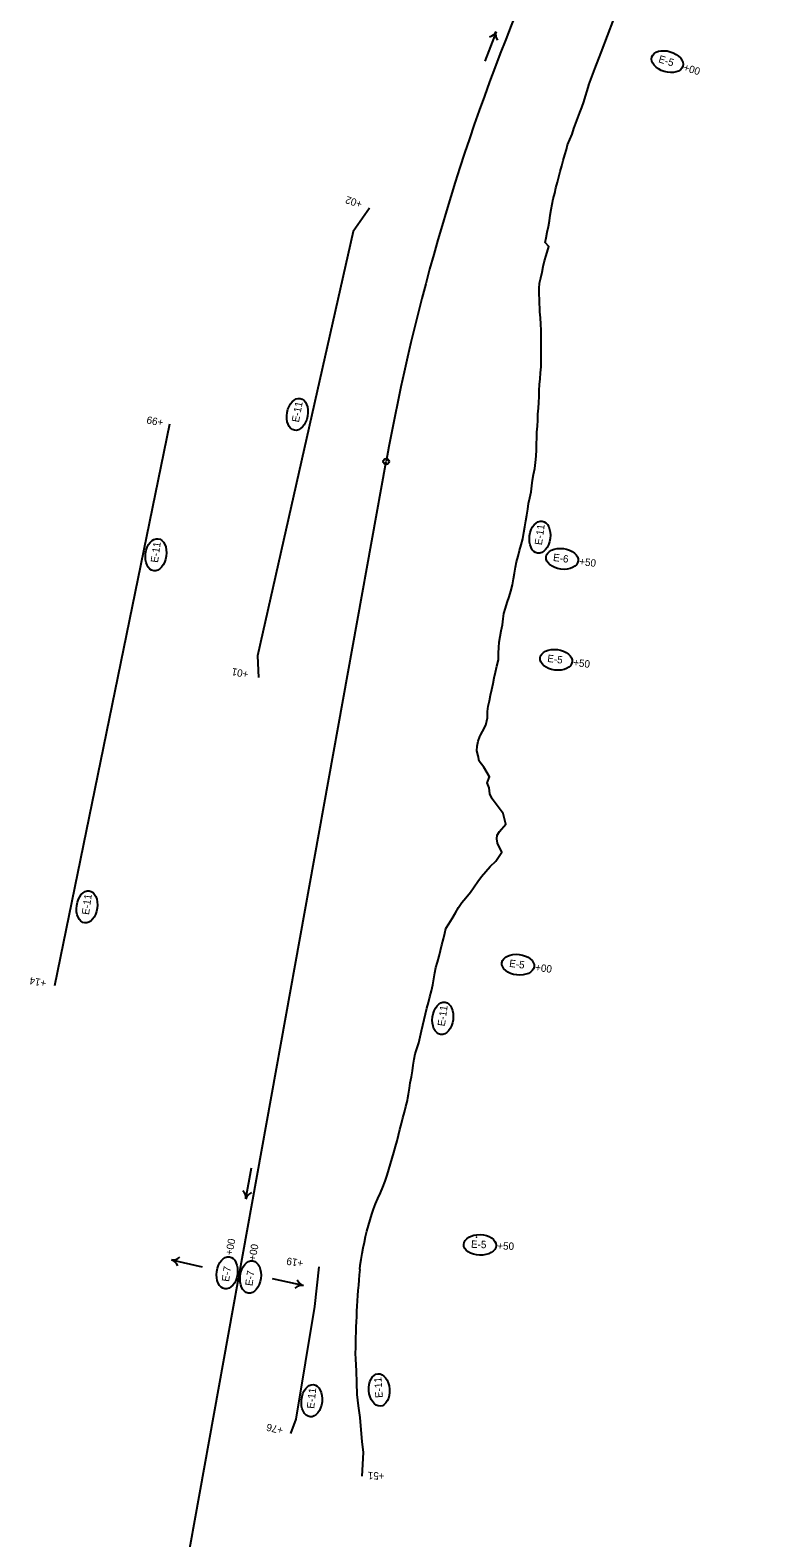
# Model space of a CAD drawing. Extents: x 669236 to 673912, y 735758 to 754788.
# Drawn here: x 670959 to 671572, y 744229 to 745505 of the extents above; entities that cross this region are included whole.
import ezdxf

# ---------------------------------------------------------------- set-up
doc = ezdxf.new("R2010")
doc.units = 0
for name, color, linetype in [('Default', 7, 'Continuous'), ('Prop_Horiz Alignment', 7, 'Continuous'), ('R_Erosion', 7, 'Continuous'), ('R_Erosion_1a', 7, 'Continuous'), ('R_Erosion_2', 7, 'Continuous'), ('R_Erosion_3', 7, 'Continuous'), ('R_Flow Arrows', 7, 'Continuous'), ('S_MSC_PT_SYM', 7, 'Continuous')]:
    doc.layers.add(name, color=color, linetype=linetype)

msp = doc.modelspace()

# ---------------------------------------------------------------- linework, layer by layer
at = {"layer": 'Default'}
msp.add_line((670962.6, 743492), (671260.2, 745139.8), dxfattribs=at)
msp.add_arc((673139.7, 744800.4), 1909.9, 145.1701, 169.7611, dxfattribs=at)
at = {"layer": 'Prop_Horiz Alignment'}
msp.add_circle((671260.2, 745139.8), 2.5, dxfattribs=at)
at = {"layer": 'R_Erosion'}
msp.add_line((671412.6, 745403.8), (671413.6, 745407.8), dxfattribs=at)
for points in [[(671431.6, 745458.5), (671436.7, 745471.9), (671442, 745485.9), (671447.3, 745500), (671452.6, 745513.9), (671457.5, 745526.2), (671463.1, 745540.1), (671469, 745553.8), (671475, 745567.6), (671480.8, 745581.5), (671486.6, 745595.3), (671492.4, 745609.1), (671498.5, 745622.7), (671504, 745634.7), (671510.1, 745648.3), (671517, 745661.5), (671517.6, 745662.6)], [(671413.6, 745407.8), (671415.5, 745412.2), (671417.4, 745416.8), (671419, 745421.4), (671420.6, 745426), (671422.2, 745430.5), (671423.9, 745435), (671425.6, 745439.4), (671427.3, 745444.1), (671428.7, 745448.9), (671430.1, 745453.5), (671431.6, 745458.3), (671431.6, 745458.5)], [(671394.8, 745325.2), (671395.5, 745329), (671396.4, 745333.7), (671397.4, 745338.5), (671398.3, 745343.3), (671399, 745348.2), (671399.8, 745353), (671400.5, 745357.6), (671401.5, 745362.1), (671402.7, 745366.7), (671403.8, 745371.4), (671405, 745376), (671406.1, 745380.6), (671407.4, 745385.2), (671408.7, 745389.9), (671409.9, 745394.5), (671411.2, 745399.2), (671412.6, 745403.8)], [(671248.6, 744504.8), (671249.4, 744507.2), (671251.3, 744511.8), (671253.2, 744516.4), (671255.3, 744521), (671257.5, 744525.8), (671259.5, 744530.9), (671261, 744536), (671262.4, 744540.7), (671263.9, 744545.5), (671265.3, 744550.4), (671266.8, 744555.3), (671268.1, 744560.2), (671269.4, 744565.1), (671270.6, 744570), (671271.9, 744574.8), (671273.2, 744579.7), (671274.4, 744584.6), (671275.6, 744589.4), (671276.9, 744594.2), (671278.2, 744599.3), (671278.6, 744601.5), (671279.1, 744604.6), (671279.8, 744609.5), (671280.6, 744614.2), (671281.6, 744619.2), (671282.4, 744624.3), (671283.1, 744629.2), (671283.9, 744634.1), (671284.6, 744638.6), (671286.1, 744643), (671287.8, 744648), (671289, 744653.1), (671290.2, 744658.1), (671291.1, 744663), (671292.3, 744667.6), (671293.6, 744672.6), (671294.7, 744677.4), (671296, 744682.2), (671297.2, 744687), (671298.6, 744691.9), (671299.8, 744697.1), (671300.6, 744702.2), (671301.5, 744707.1), (671302.3, 744711.8), (671303.5, 744716.3), (671304.9, 744721.2), (671306.1, 744726.1), (671307.4, 744730.9), (671308.7, 744735.9), (671309.7, 744740.8), (671310.8, 744744.6), (671313.3, 744748.6), (671316.1, 744753.3), (671318.8, 744757.9), (671321.4, 744762.4), (671324.1, 744766.6), (671327.6, 744770.7), (671331.5, 744775.4), (671334.5, 744780.1), (671337.7, 744784.4), (671340.9, 744788.8), (671344.4, 744793), (671348.1, 744797.1), (671353, 744801.6), (671358, 744809.3), (671354.3, 744816.9), (671353.8, 744820.5), (671354.2, 744823.6), (671356.1, 744826.9), (671361.5, 744833), (671359.1, 744842.1), (671354.2, 744848.7), (671349.9, 744854.3), (671348, 744858.6), (671347.4, 744863.7), (671345.6, 744867.9), (671347.5, 744873), (671342.8, 744881.1), (671338.9, 744886.4), (671338, 744890.7), (671336.9, 744895.1), (671337.3, 744899), (671338, 744903.3), (671339.3, 744907.2), (671340, 744908.4), (671341.6, 744911.4), (671344.5, 744916.7), (671345.9, 744922.9), (671346, 744928.3), (671346.5, 744932.7), (671347.5, 744937.4), (671348.4, 744942.1), (671349.7, 744947), (671350.7, 744952.1), (671351.6, 744956.9), (671352.8, 744961.7), (671353.8, 744966.6), (671355.1, 744972), (671355.2, 744977.6), (671355.4, 744982.5), (671355.8, 744987.1), (671356.6, 744991.8), (671357.5, 744996.6), (671358.5, 745001.7), (671359.2, 745006.8), (671359.8, 745011.3), (671361.2, 745015.6), (671362.6, 745020.5), (671364.1, 745025.3), (671365.6, 745030.2), (671366.9, 745035.4), (671367.9, 745040.5), (671368.8, 745045.4), (671369.7, 745050.3), (671370.5, 745055), (671371.8, 745059.7), (671373.1, 745064.5), (671374.4, 745069.4), (671375.7, 745074.5), (671376.6, 745079.6), (671377.4, 745084.6), (671378.2, 745089.5), (671379.1, 745094.5), (671379.9, 745099.4), (671380.7, 745104.2), (671381.7, 745109), (671382.7, 745114.2), (671383.3, 745119.3), (671383.9, 745124.1), (671384.9, 745128.8), (671385.8, 745134), (671386.4, 745139.1), (671387, 745144.3), (671387.2, 745149.6), (671387.4, 745154.7), (671387.5, 745159.7), (671387.7, 745164.6), (671388.1, 745169.6), (671388.4, 745174.7), (671388.6, 745179.8), (671388.9, 745184.8), (671389.2, 745189.7), (671389.5, 745194.8), (671389.7, 745199.9), (671389.9, 745204.9), (671390.3, 745209.7), (671390.7, 745214.7), (671391.2, 745219.8), (671391.4, 745224.1), (671391.4, 745225.2), (671391.4, 745230.3), (671391.4, 745235.5), (671391.3, 745240.6), (671391.3, 745245.7), (671391.2, 745250.9), (671391, 745256.1), (671390.6, 745261.4), (671390.2, 745266.4), (671389.9, 745276.6), (671389.6, 745281.7), (671389.5, 745286.3), (671390, 745290.7), (671391, 745295.3), (671392, 745300.1), (671393.1, 745304.9), (671394.2, 745309.6), (671395.5, 745314.2), (671397.7, 745321.6), (671394.8, 745325.2)], [(671237.9, 744456.1), (671238.2, 744460), (671239.1, 744464.8), (671240, 744469.7), (671240.9, 744474.6), (671241.8, 744479.4), (671242.8, 744484.1), (671244, 744488.7), (671245.3, 744493.4), (671246.6, 744498.2), (671248, 744502.9), (671248.6, 744504.8)], [(671234.1, 744385.4), (671234.3, 744380.4), (671234.8, 744370.4), (671235.1, 744360.4), (671235.5, 744350.5), (671236.4, 744340.8), (671238, 744330.9), (671238.9, 744320.7), (671239.7, 744310.8), (671240.8, 744301.4), (671239.7, 744281.5)]]:
    msp.add_lwpolyline(points, dxfattribs=at)
msp.add_arc((672103, 744374.4), 869, 174.6027, 179.2708, dxfattribs=at)
for centre, major_axis in [((671390.2, 745075.8), (1.9, 13.6)), ((671308.1, 744668.7), (1.9, 13.6)), ((671254.3, 744354.3), (-1, 13.7))]:
    msp.add_ellipse(centre, major_axis=major_axis, ratio=0.638788, dxfattribs=at)
at = {"layer": 'R_Erosion_1a'}
for points in [[(671246.2, 745354.2), (671232.2, 745334.4), (671151.4, 744975.5), (671152.3, 744957.2)], [(671203.2, 744458.6), (671199.6, 744425), (671183.7, 744329.7), (671179.2, 744317.4)]]:
    msp.add_lwpolyline(points, dxfattribs=at)
for centre, major_axis in [((671185.1, 745179.7), (2.5, 13.5)), ((671197.3, 744345.2), (1.4, 13.6))]:
    msp.add_ellipse(centre, major_axis=major_axis, ratio=0.638788, dxfattribs=at)
at = {"layer": 'R_Erosion_2'}
for centre in [(671125.7, 744453.4), (671145.5, 744449.9)]:
    msp.add_ellipse(centre, major_axis=(1.9, 13.6), ratio=0.638788, dxfattribs=at)
at = {"layer": 'R_Erosion_3'}
msp.add_line((670979.9, 744696.6), (671077.3, 745171.8), dxfattribs=at)
for centre, major_axis in [((671497.9, 745478.1), (13.1, -4)), ((671065.5, 745060.9), (1.9, 13.6)), ((671409, 745057.4), (13.6, -1.7)), ((671403.9, 744972), (13.6, -1.7)), ((671007.2, 744763), (1.9, 13.6)), ((671371.7, 744714.1), (13.6, -1.7)), ((671339.5, 744477), (13.7, -0.4))]:
    msp.add_ellipse(centre, major_axis=major_axis, ratio=0.638788, dxfattribs=at)
at = {"layer": 'R_Flow Arrows'}
for p, q in [((671353.1, 745503.4), (671343.7, 745478.6)), ((671141.6, 744516), (671146.4, 744542.1)), ((671078.7, 744464.4), (671104.7, 744458.6)), ((671190.1, 744442.6), (671164.1, 744448.4))]:
    msp.add_line(p, q, dxfattribs=at)
for centre, major_axis, start_param, end_param in [((671334.4, 745511), (18.9, -7.1), 5.662936, 6.259934), ((671372, 745496.6), (-18.9, 7.1), 0.023252, 0.620249), ((671121.7, 744519.4), (19.8, -3.7), 0.023252, 0.620249), ((671161.3, 744511.9), (-19.8, 3.7), 5.662936, 6.259934), ((671073.9, 744444.8), (4.4, 19.7), 5.662936, 6.259934), ((671082.9, 744484.1), (-4.4, -19.7), 0.023252, 0.620249), ((671194.9, 744462.2), (-4.4, -19.7), 5.662936, 6.259934), ((671185.9, 744422.9), (4.4, 19.7), 0.023252, 0.620249)]:
    msp.add_ellipse(centre, major_axis=major_axis, ratio=0.5625, start_param=start_param, end_param=end_param, dxfattribs=at)
at = {"layer": 'S_MSC_PT_SYM'}
msp.add_lwpolyline([(671336.6, 744483.7), (671336.6, 744483.7), (671336.6, 744483.7), (671336.6, 744483.7), (671336.6, 744483.7), (671336.6, 744483.6), (671336.6, 744483.7), (671336.7, 744483.7)], dxfattribs=at)

# ---------------------------------------------------------------- texts
at = {"layer": 'R_Erosion'}
for s, rotation, p in [('E-11', 82.0808, (671391.9, 745068.8)), ('E-11', 82.0808, (671309.8, 744661.7)), ('+19', 170.6554, (671190.5, 744464.2)), ('E-11', 94.1582, (671257.4, 744347.8)), ('+76', 167.3637, (671173.6, 744322.9)), ('+51', 177.6256, (671259, 744284.5))]:
    msp.add_text(s, height=6.25, rotation=rotation, dxfattribs=at).set_placement(p)
at = {"layer": 'R_Erosion_1a'}
for s, rotation, p in [('+02', 161.373, (671240.5, 745360)), ('E-11', 79.2832, (671186.4, 745172.6)), ('+01', 168.8842, (671144.2, 744962.5)), ('E-11', 84.157, (671199.3, 744338.2))]:
    msp.add_text(s, height=6.25, rotation=rotation, dxfattribs=at).set_placement(p)
at = {"layer": 'R_Erosion_2'}
for s, rotation, p in [('+00', 79.2728, (671130.2, 744467.8)), ('+00', 79.2728, (671149.7, 744463.2)), ('E-7', 81.9991, (671127.3, 744445.6)), ('E-7', 81.9991, (671147.1, 744442))]:
    msp.add_text(s, height=6.25, rotation=rotation, dxfattribs=at).set_placement(p)
at = {"layer": 'R_Erosion_3'}
for s, rotation, p in [('E-5', 343.1063, (671490, 745477.7)), ('+00', 343.2719, (671511, 745470.6)), ('+99', 168.8683, (671072.3, 745175.5)), ('E-11', 82.0808, (671067.2, 745053.9)), ('E-6', 352.9715, (671401.1, 745055.7)), ('+50', 353.1371, (671423.2, 745052.3)), ('E-5', 352.9715, (671396.2, 744970.3)), ('+50', 353.1371, (671418.1, 744966.9)), ('E-11', 82.0808, (671008.9, 744756)), ('E-5', 352.9715, (671364, 744712.3)), ('+14', 169.2827, (670973.2, 744701.1)), ('+00', 353.1371, (671385.9, 744708.9)), ('E-5', 358.1494, (671331.9, 744474.6)), ('+50', 358.315, (671354.1, 744473.2))]:
    msp.add_text(s, height=6.25, rotation=rotation, dxfattribs=at).set_placement(p)

doc.saveas('drawing.dxf')
